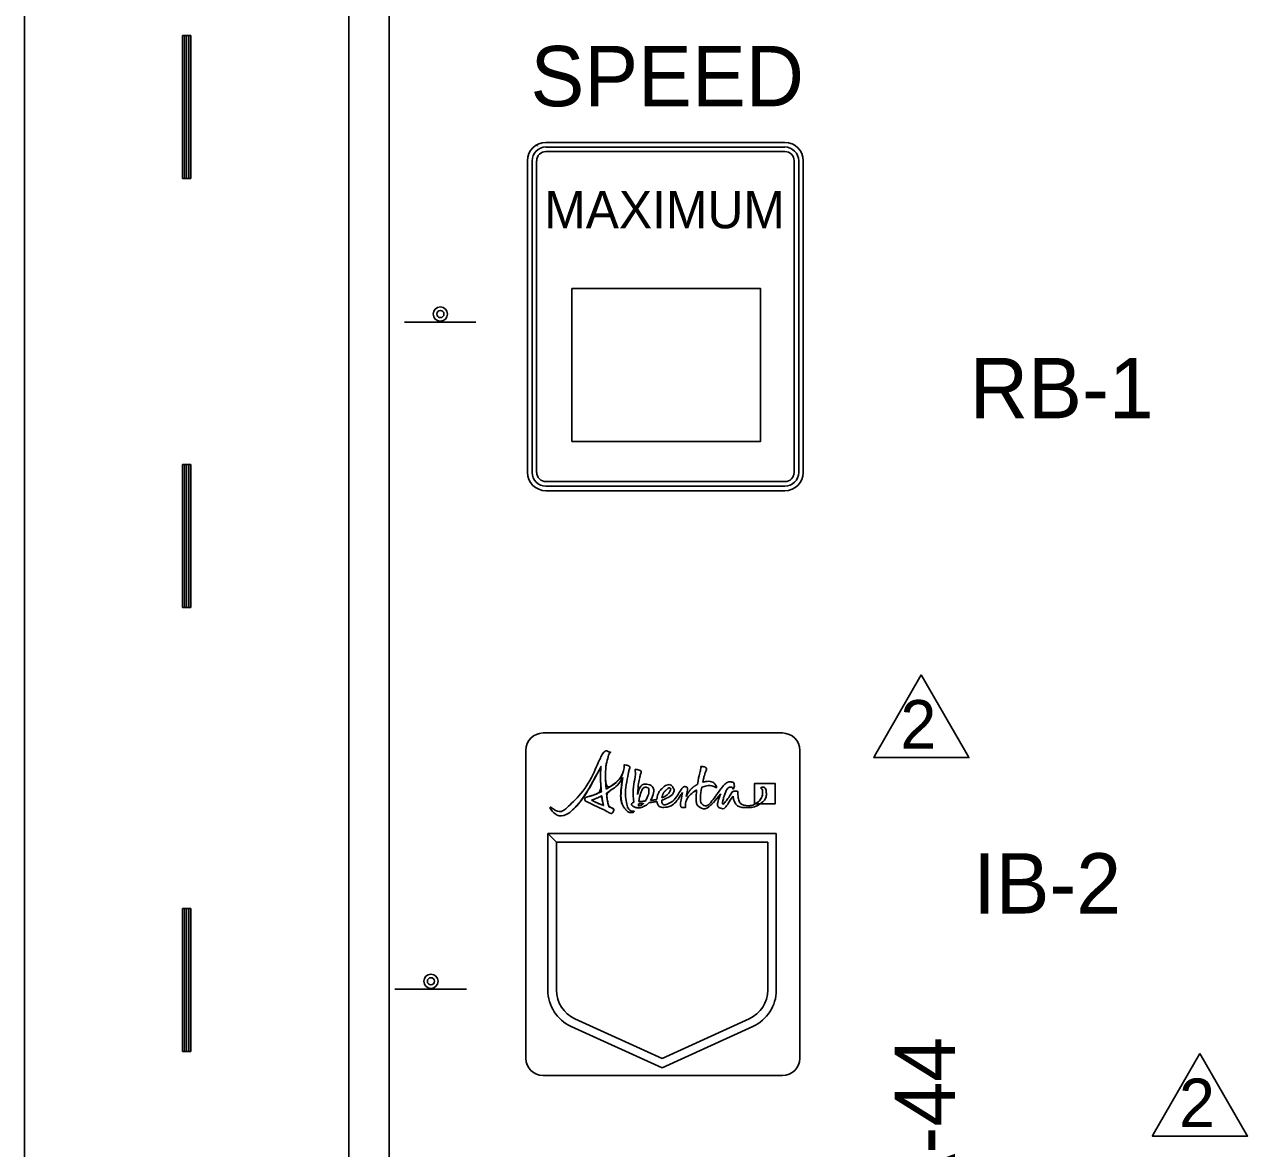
# Model space of a CAD drawing. Extents: x 1482 to 1692, y 225 to 494.
# Drawn here: x 1542.29 to 1578.78, y 408.64 to 442.18 of the extents above; entities that cross this region are included whole.
import ezdxf

# ---------------------------------------------------------------- set-up
doc = ezdxf.new("R2010")
doc.units = 0
for name, color, linetype in [('Level 17', 7, 'Continuous'), ('Level 2', 7, 'Continuous'), ('Level 53', 7, 'Continuous'), ('Level 60', 7, 'Continuous')]:
    doc.layers.add(name, color=color, linetype=linetype)

msp = doc.modelspace()

# ---------------------------------------------------------------- linework, layer by layer
at = {"layer": 'Level 17'}
for p, q in [((1557.85, 438.664), (1557.85, 438.661)), ((1557.598, 438.555), (1557.598, 438.552)), ((1557.723, 438.607), (1557.723, 438.607)), ((1557.85, 438.661), (1564.979, 438.661)), ((1557.85, 438.524), (1564.979, 438.524)), ((1557.85, 438.388), (1564.979, 438.388)), ((1557.299, 428.817), (1557.299, 438.112)), ((1557.437, 428.817), (1557.437, 438.112)), ((1557.573, 428.817), (1557.573, 438.112)), ((1565.255, 438.112), (1565.255, 428.817)), ((1565.392, 438.112), (1565.392, 428.817)), ((1565.529, 438.112), (1565.529, 428.817)), ((1553.629, 433.301), (1555.762, 433.301)), ((1564.979, 428.54), (1557.85, 428.54)), ((1564.979, 428.404), (1557.85, 428.404)), ((1564.979, 428.266), (1557.85, 428.266)), ((1553.346, 413.392), (1555.48, 413.392))]:
    msp.add_line(p, q, dxfattribs=at)
msp.add_lwpolyline([(1558.624, 434.301), (1564.254, 434.301), (1564.254, 429.74), (1558.624, 429.74)], close=True, dxfattribs=at)
for centre, radius in [((1554.7, 433.54), 0.213), ((1554.7, 433.54), 0.107), ((1554.418, 413.63), 0.213), ((1554.418, 413.63), 0.107)]:
    msp.add_circle(centre, radius, dxfattribs=at)
for centre, radius, start, end in [((1557.85, 438.113), 0.55, 90, 180), ((1564.979, 438.113), 0.55, 0, 90), ((1557.85, 438.113), 0.413, 90, 180), ((1557.85, 438.113), 0.276, 90, 180), ((1564.979, 438.113), 0.413, 0, 90), ((1564.979, 438.113), 0.276, 0, 90), ((1557.85, 428.817), 0.55, 180, 270), ((1557.85, 428.817), 0.413, 180, 270), ((1557.85, 428.817), 0.276, 180, 270), ((1564.979, 428.817), 0.55, 270, 0), ((1564.979, 428.817), 0.413, 270, 0), ((1564.979, 428.817), 0.276, 270, 0)]:
    msp.add_arc(centre, radius, start, end, dxfattribs=at)
at = {"layer": 'Level 2'}
for p, q in [((1542.29, 394.372), (1542.29, 469.813)), ((1551.968, 394.256), (1551.968, 469.813)), ((1553.177, 394.372), (1553.177, 469.813)), ((1547.001, 441.853), (1547.001, 437.586)), ((1547.001, 441.853), (1547.257, 441.853)), ((1547.065, 441.853), (1547.065, 437.586)), ((1547.129, 441.853), (1547.129, 437.586)), ((1547.193, 441.853), (1547.193, 437.586)), ((1547.257, 441.853), (1547.257, 437.586)), ((1547.001, 437.586), (1547.257, 437.586)), ((1547.001, 429.053), (1547.001, 424.787)), ((1547.001, 429.053), (1547.257, 429.053)), ((1547.065, 429.053), (1547.065, 424.787)), ((1547.129, 429.053), (1547.129, 424.787)), ((1547.193, 429.053), (1547.193, 424.787)), ((1547.257, 429.053), (1547.257, 424.787)), ((1547.001, 424.787), (1547.257, 424.787)), ((1557.765, 421.039), (1564.907, 421.039)), ((1557.765, 421.039), (1564.907, 421.039)), ((1557.247, 420.521), (1557.247, 411.334)), ((1565.425, 420.521), (1565.425, 411.334)), ((1557.907, 413.367), (1557.907, 418.035)), ((1557.907, 418.035), (1558.163, 417.779)), ((1558.163, 417.779), (1557.907, 418.035)), ((1557.907, 418.035), (1564.722, 418.035)), ((1564.722, 418.035), (1564.722, 413.367)), ((1558.163, 417.779), (1558.163, 413.367)), ((1564.467, 417.779), (1558.163, 417.779)), ((1564.467, 413.367), (1564.467, 417.779)), ((1547.001, 415.799), (1547.001, 411.532)), ((1547.001, 415.799), (1547.257, 415.799)), ((1547.065, 415.799), (1547.065, 411.532)), ((1547.129, 415.799), (1547.129, 411.532)), ((1547.193, 415.799), (1547.193, 411.532)), ((1547.257, 415.799), (1547.257, 411.532)), ((1558.712, 412.514), (1561.315, 411.33)), ((1561.315, 411.33), (1563.918, 412.514)), ((1561.315, 411.049), (1558.606, 412.281)), ((1564.023, 412.281), (1561.315, 411.049)), ((1547.001, 411.532), (1547.257, 411.532)), ((1557.765, 410.816), (1564.907, 410.816))]:
    msp.add_line(p, q, dxfattribs=at)
for centre, radius, start, end in [((1557.765, 420.521), 0.518, 90, 180), ((1564.907, 420.521), 0.518, 0, 90), ((1559.1, 413.367), 1.193, 180, 245.5432), ((1559.1, 413.367), 0.937, 180, 245.5432), ((1563.53, 413.367), 0.937, 294.4568, 0), ((1563.53, 413.367), 1.193, 294.4568, 0), ((1557.765, 411.334), 0.518, 180, 270), ((1564.907, 411.334), 0.518, 270, 0)]:
    msp.add_arc(centre, radius, start, end, dxfattribs=at)
at = {"layer": 'Level 53'}
msp.add_line((1564.245, 418.924), (1564.095, 418.924), dxfattribs=at)
msp.add_lwpolyline([(1564.245, 418.924), (1564.685, 418.924), (1564.685, 419.532), (1564.077, 419.532), (1564.077, 418.924), (1564.095, 418.924)], dxfattribs=at)
for points, degree in [([(1560.432, 418.703), (1560.367, 418.713), (1560.281, 418.802), (1560.255, 418.948), (1560.208, 419.212), (1560.236, 419.472), (1560.314, 419.859), (1560.328, 419.932), (1560.378, 420.059), (1560.219, 420.084), (1560.169, 420.092), (1560.195, 420.067), (1560.181, 420), (1560.119, 419.711), (1559.883, 419.503), (1559.647, 419.364), (1559.622, 419.694), (1559.632, 420.061), (1559.694, 420.286), (1559.747, 420.476), (1559.809, 420.441), (1559.732, 420.481), (1559.65, 420.523), (1559.563, 420.467), (1559.492, 420.326), (1559.421, 420.185), (1559.095, 419.417), (1558.574, 418.899), (1558.307, 418.634), (1558.066, 418.77), (1558.018, 418.811), (1557.978, 418.844), (1557.964, 418.793), (1558.012, 418.74), (1558.228, 418.508), (1558.543, 418.641), (1558.658, 418.756), (1558.975, 419.073), (1559.343, 419.755), (1559.493, 420.044), (1559.479, 419.881), (1559.474, 419.608), (1559.505, 419.288), (1559.343, 419.209), (1559.199, 419.163), (1559.13, 419.145), (1559.056, 419.126), (1559.011, 419.096), (1559.009, 419.061), (1559.008, 419.024), (1559.058, 418.992), (1559.129, 418.958), (1559.257, 418.898), (1559.631, 418.721), (1559.723, 418.667), (1559.802, 418.621), (1559.841, 418.657), (1559.864, 418.707), (1559.894, 418.771), (1559.811, 418.808), (1559.73, 418.832), (1559.698, 418.941), (1559.673, 419.087), (1559.657, 419.248), (1559.847, 419.365), (1560.034, 419.521), (1560.142, 419.715), (1560.115, 419.553), (1560.045, 418.999), (1560.22, 418.765), (1560.258, 418.713), (1560.343, 418.657), (1560.426, 418.665), (1560.465, 418.669), (1560.485, 418.695), (1560.481, 418.703), (1560.477, 418.711), (1560.455, 418.7), (1560.432, 418.703)], 3), ([(1559.647, 419.364), (1559.622, 419.694), (1559.632, 420.061), (1559.694, 420.286), (1559.747, 420.476), (1559.809, 420.441), (1559.732, 420.481), (1559.65, 420.523), (1559.563, 420.467), (1559.492, 420.326), (1559.421, 420.185), (1559.095, 419.417), (1558.574, 418.899), (1558.307, 418.634), (1558.066, 418.77), (1558.018, 418.811), (1557.978, 418.844), (1557.964, 418.793), (1558.012, 418.74), (1558.228, 418.508), (1558.543, 418.641), (1558.658, 418.756), (1558.975, 419.073), (1559.343, 419.755), (1559.493, 420.044)], 3), ([(1560.432, 418.703), (1560.367, 418.713), (1560.281, 418.802), (1560.255, 418.948), (1560.208, 419.212), (1560.236, 419.472), (1560.314, 419.859), (1560.328, 419.932), (1560.378, 420.059), (1560.219, 420.084), (1560.169, 420.092), (1560.195, 420.067), (1560.181, 420), (1560.119, 419.711), (1559.883, 419.503), (1559.647, 419.364)], 3), ([(1559.493, 420.044), (1559.479, 419.881), (1559.474, 419.608), (1559.505, 419.288)], 2), ([(1559.657, 419.248), (1559.847, 419.365), (1560.034, 419.521), (1560.142, 419.715)], 2), ([(1560.142, 419.715), (1560.115, 419.553), (1560.045, 418.999), (1560.22, 418.765), (1560.258, 418.713), (1560.343, 418.657), (1560.426, 418.665), (1560.465, 418.669), (1560.485, 418.695), (1560.481, 418.703), (1560.477, 418.711), (1560.455, 418.7), (1560.432, 418.703)], 3), ([(1560.578, 419.205), (1560.591, 419.36), (1560.616, 419.549), (1560.651, 419.724), (1560.665, 419.798), (1560.716, 419.925), (1560.556, 419.949), (1560.506, 419.957), (1560.514, 419.933), (1560.518, 419.865), (1560.524, 419.773), (1560.422, 419.217), (1560.475, 418.973)], 3), ([(1562.529, 419.571), (1562.546, 419.652), (1562.567, 419.734), (1562.589, 419.814), (1562.61, 419.888), (1562.67, 420.015), (1562.513, 420.039), (1562.463, 420.047), (1562.484, 420.023), (1562.468, 419.955), (1562.437, 419.83), (1562.399, 419.669), (1562.371, 419.506)], 3), ([(1560.97, 419.025), (1561.083, 419.208), (1561.074, 419.456), (1560.908, 419.498), (1560.716, 419.547), (1560.619, 419.36), (1560.578, 419.205)], 3), ([(1560.619, 418.99), (1560.645, 419.185), (1560.747, 419.456), (1560.873, 419.412), (1560.946, 419.387), (1560.908, 419.159), (1560.814, 419.007)], 3), ([(1561.305, 419.031), (1561.331, 419.039), (1561.354, 419.047), (1561.374, 419.056), (1561.615, 419.163), (1561.697, 419.324), (1561.636, 419.422), (1561.578, 419.515), (1561.412, 419.487), (1561.281, 419.348), (1561.217, 419.28), (1561.167, 419.164), (1561.161, 419.057)], 3), ([(1562.034, 419.144), (1562.049, 419.219), (1562.073, 419.303), (1562.074, 419.359), (1562.076, 419.418), (1562.035, 419.432), (1562.02, 419.436), (1561.985, 419.446), (1561.944, 419.429), (1561.902, 419.371), (1561.806, 419.235), (1561.684, 419.021), (1561.499, 418.931), (1561.366, 418.866), (1561.308, 418.931), (1561.305, 419.031)], 3), ([(1561.433, 419.336), (1561.514, 419.411), (1561.554, 419.406), (1561.565, 419.386), (1561.588, 419.342), (1561.493, 419.189), (1561.311, 419.105)], 3), ([(1561.311, 419.105), (1561.326, 419.187), (1561.37, 419.277), (1561.433, 419.336)], 2), ([(1561.921, 419.264), (1561.907, 419.118), (1561.812, 418.798), (1561.975, 418.815), (1562.038, 418.821), (1562.01, 418.831), (1562.014, 418.886), (1562.028, 419.079), (1562.189, 419.242), (1562.347, 419.342)], 3), ([(1562.371, 419.506), (1562.242, 419.432), (1562.122, 419.308), (1562.034, 419.144)], 2), ([(1562.347, 419.342), (1562.32, 419.106), (1562.329, 418.896), (1562.436, 418.829), (1562.633, 418.706), (1562.912, 419.03), (1563.065, 419.228)], 3), ([(1563.907, 418.87), (1563.657, 418.87), (1563.593, 419.064), (1563.581, 419.16), (1563.573, 419.224), (1563.586, 419.316), (1563.476, 419.304), (1563.399, 419.295), (1563.329, 419.145), (1563.231, 419.018), (1563.147, 418.91), (1563.11, 418.92), (1563.129, 419.013), (1563.154, 419.13), (1563.251, 419.404), (1563.363, 419.424), (1563.414, 419.433), (1563.433, 419.343), (1563.457, 419.399), (1563.48, 419.456), (1563.458, 419.579), (1563.343, 419.579), (1563.262, 419.579), (1563.165, 419.493), (1563.086, 419.395), (1563.016, 419.31), (1562.666, 418.795), (1562.519, 418.906), (1562.45, 418.958), (1562.456, 419.17), (1562.499, 419.42)], 3), ([(1562.499, 419.42), (1562.673, 419.487), (1562.819, 419.465), (1562.901, 419.426), (1562.941, 419.406), (1562.947, 419.409), (1562.929, 419.454), (1562.904, 419.519), (1562.764, 419.621), (1562.544, 419.574), (1562.539, 419.573), (1562.534, 419.572), (1562.529, 419.571)], 3), ([(1564.077, 419.532), (1564.077, 419.532), (1564.077, 418.924), (1564.077, 418.924), (1564.077, 418.924), (1564.095, 418.924), (1564.095, 418.924), (1564.227, 419.003), (1564.315, 419.154), (1564.315, 419.278), (1564.315, 419.385), (1564.258, 419.38), (1564.265, 419.395), (1564.283, 419.438), (1564.417, 419.414), (1564.425, 419.262), (1564.432, 419.133), (1564.365, 419.009), (1564.245, 418.924), (1564.245, 418.924), (1564.685, 418.924), (1564.685, 418.924), (1564.685, 418.924), (1564.685, 419.532), (1564.685, 419.532), (1564.685, 419.532), (1564.077, 419.532), (1564.077, 419.532)], 3), ([(1564.095, 418.924), (1564.227, 419.003), (1564.315, 419.154), (1564.315, 419.278), (1564.315, 419.385), (1564.258, 419.38), (1564.265, 419.395), (1564.283, 419.438), (1564.417, 419.414), (1564.425, 419.262), (1564.432, 419.133), (1564.365, 419.009), (1564.245, 418.924)], 3), ([(1559.505, 419.288), (1559.343, 419.209), (1559.199, 419.163), (1559.13, 419.145), (1559.056, 419.126), (1559.011, 419.096), (1559.009, 419.061), (1559.008, 419.024), (1559.058, 418.992), (1559.129, 418.958), (1559.257, 418.898), (1559.631, 418.721), (1559.723, 418.667), (1559.802, 418.621), (1559.841, 418.657), (1559.864, 418.707), (1559.894, 418.771), (1559.811, 418.808), (1559.73, 418.832)], 3), ([(1559.213, 419.033), (1559.297, 419.064), (1559.404, 419.109), (1559.517, 419.168)], 2), ([(1559.213, 419.033), (1559.297, 419.064), (1559.404, 419.109), (1559.517, 419.168), (1559.532, 419.04), (1559.549, 418.946), (1559.567, 418.877), (1559.485, 418.907), (1559.367, 418.955), (1559.213, 419.033)], 3), ([(1559.567, 418.877), (1559.485, 418.907), (1559.367, 418.955), (1559.213, 419.033)], 2), ([(1559.517, 419.168), (1559.532, 419.04), (1559.549, 418.946), (1559.567, 418.877)], 2), ([(1559.73, 418.832), (1559.698, 418.941), (1559.673, 419.087), (1559.657, 419.248)], 2), ([(1560.475, 418.973), (1560.406, 418.951), (1560.379, 418.899), (1560.467, 418.845), (1560.527, 418.807), (1560.661, 418.795), (1560.796, 418.861), (1560.844, 418.885), (1560.886, 418.919), (1560.921, 418.958)], 3), ([(1560.814, 419.007), (1560.753, 419.001), (1560.688, 418.995), (1560.619, 418.99)], 2), ([(1560.921, 418.958), (1561.002, 418.969), (1561.086, 418.981), (1561.163, 418.997)], 2), ([(1561.161, 419.057), (1561.106, 419.045), (1561.042, 419.034), (1560.97, 419.025)], 2), ([(1561.163, 418.997), (1561.176, 418.89), (1561.246, 418.808), (1561.408, 418.823), (1561.639, 418.844), (1561.844, 419.128), (1561.921, 419.264)], 3), ([(1563.065, 419.228), (1562.987, 419.052), (1562.943, 418.826), (1563.061, 418.792), (1563.198, 418.752), (1563.307, 418.98), (1563.434, 419.155)], 3), ([(1563.434, 419.155), (1563.448, 419.029), (1563.532, 418.813), (1563.869, 418.813), (1564.021, 418.813), (1564.149, 418.856), (1564.245, 418.924)], 3), ([(1560.599, 418.872), (1560.608, 418.879), (1560.613, 418.89), (1560.613, 418.903), (1560.613, 418.912), (1560.613, 418.92), (1560.614, 418.929)], 3), ([(1560.654, 418.872), (1560.632, 418.869), (1560.613, 418.869), (1560.599, 418.872)], 2), ([(1560.614, 418.929), (1560.648, 418.931), (1560.702, 418.935), (1560.765, 418.941)], 2), ([(1560.765, 418.941), (1560.732, 418.904), (1560.694, 418.878), (1560.654, 418.872)], 2), ([(1564.095, 418.924), (1564.039, 418.89), (1563.975, 418.87), (1563.907, 418.87)], 2)]:
    msp.add_open_spline(points, degree=degree, dxfattribs=at)
at = {"layer": 'Level 60'}
for points in [[(1569.051, 422.775), (1567.658, 420.35)], [(1570.445, 420.35), (1569.051, 422.775)], [(1567.658, 420.35), (1567.632, 420.305), (1570.471, 420.305), (1570.445, 420.35)], [(1577.364, 411.479), (1575.971, 409.054)], [(1578.758, 409.054), (1577.364, 411.479)], [(1575.971, 409.054), (1575.945, 409.009), (1578.784, 409.009), (1578.758, 409.054)]]:
    msp.add_lwpolyline(points, dxfattribs=at)

# ---------------------------------------------------------------- texts
at = {"layer": 'Level 17'}
for s, rotation, p in [('SPEED', 360, (1557.389, 439.741)), ('RB-1', 360, (1570.499, 430.43)), ('IB-2', 360, (1570.599, 415.652)), ('WD-A-44', 90, (1570.06, 402.073))]:
    msp.add_text(s, height=1.8, rotation=rotation, dxfattribs=at).set_placement(p)
msp.add_text('MAXIMUM', height=1.1106, dxfattribs=at).set_placement((1557.8, 436.099))
at = {"layer": 'Level 60'}
for p in [(1568.424, 420.574), (1576.737, 409.278)]:
    msp.add_text('2', height=1.448, rotation=360, dxfattribs=at).set_placement(p)

doc.saveas('drawing.dxf')
